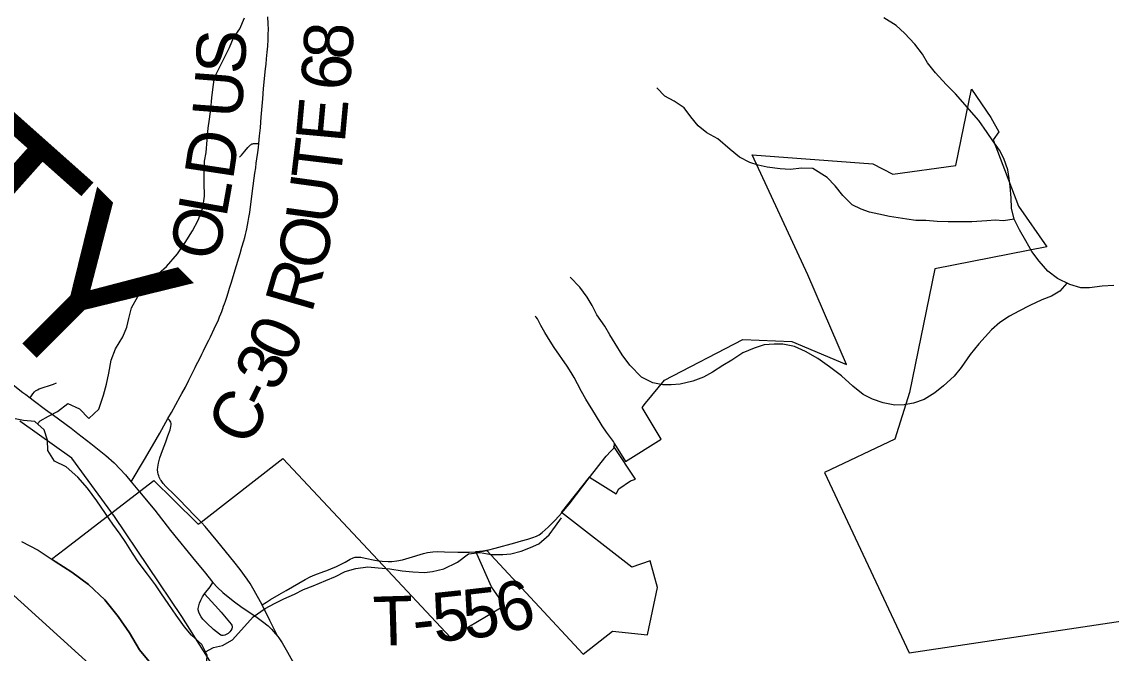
# Model space of a CAD drawing. Extents: x 0 to 34, y 0 to 22.
# Drawn here: x 4.632 to 5.89, y 17.888 to 18.618 of the extents above; entities that cross this region are included whole.
import ezdxf

# ---------------------------------------------------------------- set-up
doc = ezdxf.new("R2010")
doc.units = 0
for name, color, linetype in [('Default', 7, 'Continuous'), ('GM_X_City_Street', 7, 'Continuous'), ('GM_X_Corporation', 7, 'Continuous'), ('GM_X_County_Road', 7, 'Continuous'), ('GM_X_County_Road_Text', 7, 'Continuous'), ('GM_X_County_Text', 7, 'Continuous'), ('GM_X_Major_River', 7, 'Continuous'), ('GM_X_Minor_River', 7, 'Continuous'), ('GM_X_Rail_Line', 7, 'Continuous'), ('GM_X_Township_Road', 7, 'Continuous'), ('GM_X_Township_Road_Text', 7, 'Continuous'), ('GM_X_US_Route', 7, 'Continuous'), ('SH_Cut_Line', 7, 'Continuous'), ('SH_Text', 7, 'Continuous')]:
    doc.layers.add(name, color=color, linetype=linetype)

msp = doc.modelspace()

# ---------------------------------------------------------------- linework, layer by layer
at = {"layer": 'Default'}
msp.add_lwpolyline([(4.6315, 18.0174), (4.6508, 18.0075), (4.6705, 17.9942), (4.6895, 17.9821), (4.7088, 17.9676), (4.7278, 17.9502), (4.7433, 17.9308), (4.7562, 17.9118), (4.7676, 17.8924), (4.7846, 17.8719)], dxfattribs=at)
at = {"layer": 'GM_X_City_Street'}
msp.add_lwpolyline([(4.8429, 17.9568), (4.8588, 17.9394), (4.8621, 17.9356), (4.8736, 17.9218), (4.8742, 17.9208), (4.8746, 17.919), (4.8747, 17.9177), (4.8743, 17.9166), (4.8731, 17.9144), (4.872, 17.9129), (4.8701, 17.9113), (4.868, 17.9099), (4.8663, 17.9092), (4.8645, 17.9088), (4.8627, 17.9089), (4.8615, 17.9093), (4.86, 17.9103), (4.8531, 17.9157), (4.8455, 17.9229), (4.8408, 17.9278), (4.8389, 17.9303), (4.8374, 17.933), (4.8362, 17.9359), (4.8356, 17.9383), (4.8356, 17.9402), (4.8361, 17.9432), (4.837, 17.9462), (4.8385, 17.9496), (4.8406, 17.9534), (4.8429, 17.9568), (4.8495, 17.965), (4.8525, 17.9701)], dxfattribs=at)
at = {"layer": 'GM_X_Corporation'}
msp.add_lwpolyline([(4.7846, 17.8719), (4.7676, 17.8924), (4.7562, 17.9118), (4.7433, 17.9308), (4.7278, 17.9502), (4.7088, 17.9676), (4.6895, 17.9821), (4.6663, 17.9971), (4.6822, 18.0093), (4.7676, 18.0753), (4.7844, 18.0881), (4.8072, 18.0655), (4.8356, 18.0375), (4.8391, 18.0399), (4.8408, 18.0412), (4.9332, 18.1133), (5.0434, 17.9957), (5.1269, 17.9065), (5.1893, 17.9436), (5.1743, 17.9652), (5.156, 18.0059), (5.1642, 18.0067), (5.1685, 18.0075), (5.2802, 17.8874), (5.3138, 17.9139), (5.3542, 17.9096), (5.3658, 17.9643), (5.3573, 17.995), (5.3363, 17.9878), (5.2549, 18.0509), (5.2872, 18.0918), (5.3182, 18.0725), (5.3211, 18.0782), (5.3347, 18.0874), (5.3403, 18.0894), (5.3156, 18.1272), (5.3161, 18.1289), (5.3161, 18.1302), (5.3291, 18.11), (5.37, 18.1357), (5.348, 18.1723), (5.3521, 18.1772), (5.3739, 18.2038), (5.4644, 18.2508), (5.5208, 18.2485), (5.584, 18.2221), (5.5394, 18.3257), (5.4753, 18.4644), (5.6144, 18.4541), (5.6375, 18.4422), (5.7102, 18.452), (5.7284, 18.5403), (5.7506, 18.5077), (5.7599, 18.4908), (5.7535, 18.4818), (5.7825, 18.4049), (5.8153, 18.3581), (5.6861, 18.3327), (5.657, 18.1896), (5.6398, 18.1359), (5.5587, 18.0971), (5.6566, 17.8886), (5.9367, 17.9306)], dxfattribs=at)
at = {"layer": 'GM_X_County_Road'}
for points in [[(4.9056, 18.4775), (4.9065, 18.4865), (4.9074, 18.4954), (4.9079, 18.5023), (4.9084, 18.5078), (4.9102, 18.529), (4.9111, 18.5409), (4.9133, 18.5636), (4.9139, 18.5693), (4.9145, 18.5752), (4.9152, 18.5829), (4.9158, 18.5901), (4.9162, 18.5977), (4.9165, 18.6034), (4.9166, 18.6095), (4.9164, 18.6156), (4.9158, 18.6237)], [(4.8006, 18.1596), (4.8046, 18.1665), (4.8148, 18.1849), (4.8168, 18.1887), (4.8207, 18.1958), (4.8249, 18.2041), (4.8299, 18.214), (4.8321, 18.2185), (4.8337, 18.2219), (4.8365, 18.2274), (4.8397, 18.2341), (4.8416, 18.238), (4.8446, 18.2442), (4.8477, 18.2503), (4.8496, 18.2542), (4.8539, 18.2631), (4.8588, 18.2738), (4.8603, 18.2771), (4.8617, 18.2806), (4.8628, 18.2834), (4.8639, 18.2866), (4.8649, 18.2896), (4.8658, 18.292), (4.8669, 18.2953), (4.8684, 18.2997), (4.8701, 18.3048), (4.8718, 18.3101), (4.8739, 18.3172), (4.8781, 18.3316), (4.8838, 18.3503), (4.886, 18.3575), (4.8883, 18.365), (4.8893, 18.3688), (4.8902, 18.3721), (4.8909, 18.3752), (4.8917, 18.3789), (4.8926, 18.383), (4.8934, 18.3873), (4.8941, 18.3919), (4.895, 18.3978), (4.8959, 18.4041), (4.8972, 18.4131), (4.8984, 18.4228), (4.9011, 18.4433), (4.9019, 18.4495), (4.9026, 18.4546), (4.9033, 18.4597), (4.9043, 18.4671), (4.9051, 18.473), (4.9056, 18.4775)], [(4.7583, 18.0865), (4.7737, 18.1122), (4.7828, 18.1281), (4.7911, 18.1428), (4.8006, 18.1596)]]:
    msp.add_lwpolyline(points, dxfattribs=at)
at = {"layer": 'GM_X_Major_River'}
for points in [[(4.7663, 17.994), (4.7596, 18.0039), (4.7518, 18.0162), (4.7455, 18.0258), (4.737, 18.0373), (4.7284, 18.0499), (4.7184, 18.0644), (4.7079, 18.079), (4.6964, 18.0917), (4.6829, 18.1036), (4.6697, 18.1102), (4.6619, 18.1225), (4.6617, 18.1346), (4.6577, 18.1465), (4.6468, 18.1561), (4.6339, 18.1574), (4.6241, 18.1594)], [(4.8727, 17.8128), (4.8582, 17.8361), (4.8535, 17.8479), (4.8502, 17.8605), (4.8451, 17.8723), (4.846, 17.8859), (4.8397, 17.8985), (4.8277, 17.9093), (4.8199, 17.9189), (4.8102, 17.9323), (4.8017, 17.9446), (4.7924, 17.958), (4.7864, 17.9675), (4.7771, 17.9798), (4.7663, 17.994)]]:
    msp.add_lwpolyline(points, dxfattribs=at)
at = {"layer": 'GM_X_Minor_River'}
for points in [[(4.6499, 18.1533), (4.653, 18.1568), (4.6626, 18.1624), (4.6729, 18.1679), (4.6851, 18.1769), (4.6983, 18.1706), (4.7092, 18.1595), (4.7207, 18.1703), (4.7262, 18.1866), (4.7297, 18.1994), (4.7322, 18.2119), (4.735, 18.227), (4.7401, 18.2402), (4.7486, 18.2542), (4.7533, 18.2651), (4.7553, 18.2753), (4.7585, 18.2874), (4.7659, 18.3006), (4.7767, 18.3141), (4.7863, 18.3242), (4.7989, 18.3354), (4.8116, 18.35), (4.8205, 18.3632), (4.829, 18.3767), (4.8356, 18.3888), (4.8407, 18.4031), (4.8428, 18.4164), (4.8426, 18.4323), (4.8424, 18.4448), (4.8429, 18.457), (4.8446, 18.4672), (4.8459, 18.4816), (4.8472, 18.4952), (4.8485, 18.5054), (4.8501, 18.5172), (4.8514, 18.5304), (4.8527, 18.5429), (4.8544, 18.5539), (4.8614, 18.5678), (4.8664, 18.5776), (4.8715, 18.5886), (4.8762, 18.5995), (4.8835, 18.61), (4.889, 18.6228)], [(5.8928, 18.3133), (5.8792, 18.3124), (5.8647, 18.3107), (5.8545, 18.3108), (5.842, 18.3144), (5.8277, 18.3214), (5.8165, 18.3299), (5.8064, 18.3414), (5.7982, 18.3525), (5.7911, 18.3651), (5.7837, 18.3777), (5.7778, 18.39), (5.7745, 18.4029), (5.7743, 18.4147), (5.7729, 18.4276), (5.7719, 18.4371), (5.7702, 18.4469), (5.7658, 18.4603), (5.7606, 18.4698), (5.7531, 18.4805), (5.7464, 18.4901), (5.7368, 18.5039), (5.7285, 18.5135), (5.7184, 18.5254), (5.7098, 18.535), (5.699, 18.5457), (5.687, 18.5592), (5.6777, 18.5707), (5.6718, 18.5806), (5.6628, 18.5921), (5.6512, 18.6048), (5.6415, 18.614), (5.6272, 18.6229)], [(5.7777, 18.3902), (5.7652, 18.3882), (5.7558, 18.3887), (5.7463, 18.3881), (5.7288, 18.3868), (5.711, 18.387), (5.7015, 18.3868), (5.6887, 18.3873), (5.6758, 18.3883), (5.664, 18.3884), (5.6538, 18.3901), (5.6436, 18.3914), (5.6338, 18.393), (5.6213, 18.3958), (5.6107, 18.3982), (5.6009, 18.4014), (5.5907, 18.4065), (5.5798, 18.4172), (5.5709, 18.4287), (5.5619, 18.4383), (5.5454, 18.4484), (5.5325, 18.449), (5.5192, 18.4476), (5.5074, 18.4482), (5.4923, 18.4503), (5.4821, 18.4523), (5.4723, 18.4555), (5.4606, 18.4617), (5.4497, 18.4705), (5.4355, 18.4829), (5.4227, 18.4899), (5.4129, 18.498), (5.4043, 18.5083), (5.3965, 18.5187), (5.3852, 18.5264), (5.3743, 18.5322), (5.3649, 18.5418)], [(5.8384, 18.3162), (5.8306, 18.3066), (5.8206, 18.301), (5.8096, 18.2966), (5.7959, 18.2903), (5.7829, 18.2837), (5.7722, 18.2778), (5.7611, 18.2707), (5.7515, 18.2621), (5.7369, 18.246), (5.7269, 18.2336), (5.7165, 18.2186), (5.7084, 18.2085), (5.6961, 18.1972), (5.6862, 18.1894), (5.6736, 18.1816), (5.6614, 18.1772), (5.6507, 18.1755), (5.6397, 18.1752), (5.6265, 18.1777), (5.614, 18.182), (5.6035, 18.1875), (5.5915, 18.1971), (5.5784, 18.209), (5.5645, 18.2195), (5.5509, 18.2291), (5.5366, 18.2369), (5.5242, 18.2428), (5.5106, 18.2456), (5.5007, 18.2457), (5.489, 18.2447), (5.4775, 18.2411), (5.4642, 18.2356), (5.4516, 18.227), (5.4413, 18.2207), (5.4294, 18.2133), (5.4191, 18.2074), (5.4065, 18.2026), (5.3921, 18.1994), (5.3815, 18.1984), (5.372, 18.1985), (5.3603, 18.2009), (5.3474, 18.2072), (5.334, 18.2214), (5.325, 18.2333), (5.3169, 18.2463), (5.3109, 18.2562), (5.305, 18.2665), (5.296, 18.2795), (5.2905, 18.2902), (5.2845, 18.2998), (5.2763, 18.3113), (5.2651, 18.3228)], [(4.8439, 17.8901), (4.8533, 17.8948), (4.8636, 17.8973), (4.875, 17.9039), (4.8989, 17.9302), (4.913, 17.9399), (4.9237, 17.9458), (4.9344, 17.951), (4.9466, 17.9565), (4.9573, 17.962), (4.9683, 17.9664), (4.9828, 17.9723), (4.9942, 17.9771), (5.0053, 17.9826), (5.0175, 17.9863), (5.0315, 17.988), (5.0433, 17.9871), (5.0569, 17.9857), (5.0709, 17.9837), (5.0834, 17.9824), (5.0967, 17.9818), (5.1062, 17.9828), (5.1191, 17.9857), (5.1351, 17.9934), (5.1477, 18.0031), (5.161, 18.0048), (5.1739, 18.0024), (5.1872, 18.0026), (5.1966, 18.0032), (5.2084, 18.0061), (5.2191, 18.0105), (5.229, 18.0146), (5.2409, 18.025), (5.2482, 18.0352), (5.2552, 18.0449)]]:
    msp.add_lwpolyline(points, dxfattribs=at)
at = {"layer": 'GM_X_Rail_Line'}
msp.add_lwpolyline([(5.3956, 16.5475), (5.3342, 16.7534), (5.2911, 16.8846), (5.2194, 17.0664), (5.139, 17.2492), (5.1192, 17.3014), (5.1029, 17.346), (5.0833, 17.3922), (5.0098, 17.5633), (4.954, 17.6832), (4.8916, 17.8118), (4.8168, 17.9308), (4.739, 18.0464), (4.6895, 18.1137), (4.6296, 18.1567)], dxfattribs=at)
at = {"layer": 'GM_X_Township_Road'}
msp.add_line((5.3158, 18.1266), (5.3163, 18.1284), dxfattribs=at)
for points in [[(4.8832, 18.4615), (4.8855, 18.4641), (4.8893, 18.4687), (4.8928, 18.4729), (4.894, 18.4741), (4.8954, 18.4755), (4.8961, 18.476), (4.8968, 18.4765), (4.8976, 18.4769), (4.8985, 18.4772), (4.8994, 18.4774), (4.9003, 18.4775), (4.902, 18.4775), (4.9056, 18.4775)], [(5.3163, 18.1284), (5.3164, 18.1297), (5.316, 18.1314), (5.3152, 18.1331), (5.3069, 18.144), (5.3021, 18.1512), (5.2944, 18.1639), (5.2832, 18.1818), (5.278, 18.191), (5.2733, 18.1997), (5.2696, 18.2069), (5.2662, 18.2128), (5.2615, 18.2201), (5.2467, 18.2416), (5.2419, 18.2489), (5.2357, 18.2589), (5.2311, 18.267), (5.2272, 18.2747), (5.2258, 18.2768), (5.2245, 18.278)], [(4.6415, 18.1836), (4.6446, 18.188), (4.6464, 18.1904), (4.6477, 18.1916), (4.6498, 18.1929), (4.652, 18.194), (4.6567, 18.1955), (4.6639, 18.1977), (4.6686, 18.1994), (4.6719, 18.201)], [(4.7904, 18.0919), (4.7899, 18.0934), (4.7894, 18.0952), (4.7889, 18.0976), (4.7887, 18.1001), (4.7888, 18.1032), (4.7897, 18.108), (4.7913, 18.1141), (4.7943, 18.1228), (4.7981, 18.1327), (4.8006, 18.1397), (4.8031, 18.1467), (4.8041, 18.1502), (4.8043, 18.1525), (4.8043, 18.1539), (4.804, 18.1554), (4.8033, 18.1565), (4.8024, 18.1576), (4.8006, 18.1596)], [(5.2871, 18.091), (5.2927, 18.0982), (5.3009, 18.1089), (5.3067, 18.1159), (5.312, 18.1218), (5.3149, 18.125), (5.3158, 18.1266)], [(4.8393, 18.0394), (4.8315, 18.0473), (4.8136, 18.0661), (4.8079, 18.0718), (4.798, 18.0811), (4.7951, 18.0843), (4.7926, 18.0878), (4.792, 18.0887), (4.7915, 18.0896), (4.7904, 18.0919)], [(5.2553, 18.0506), (5.2574, 18.053), (5.2638, 18.0605), (5.2724, 18.0717), (5.2859, 18.0894), (5.2871, 18.091)], [(4.9093, 17.9441), (4.9003, 17.961), (4.8956, 17.969), (4.892, 17.9741), (4.884, 17.9851), (4.8767, 17.9944), (4.8583, 18.017), (4.8436, 18.0347), (4.8393, 18.0394)], [(5.1697, 18.0073), (5.1786, 18.0098), (5.2013, 18.016), (5.209, 18.0183), (5.2161, 18.0203), (5.222, 18.0222), (5.226, 18.0235), (5.2293, 18.0251), (5.2325, 18.0278), (5.2396, 18.0341), (5.2477, 18.042), (5.2553, 18.0506)], [(5.0447, 17.9951), (5.0478, 17.9948), (5.0547, 17.9944), (5.059, 17.9945), (5.065, 17.9952), (5.0715, 17.9964), (5.0792, 17.9984), (5.0955, 18.0036), (5.1003, 18.0047), (5.1065, 18.0055), (5.112, 18.0058), (5.1201, 18.0057), (5.1355, 18.0051), (5.1484, 18.0053)], [(5.1484, 18.0053), (5.1563, 18.0054), (5.1573, 18.0055)], [(5.1573, 18.0055), (5.1644, 18.0062), (5.1687, 18.007), (5.1697, 18.0073)], [(4.9093, 17.9441), (4.9143, 17.9473), (4.9191, 17.9503), (4.9292, 17.9563), (4.9372, 17.961), (4.959, 17.9736), (4.965, 17.9767), (4.9701, 17.979), (4.9805, 17.9828), (4.984, 17.9841), (4.9885, 17.986), (4.9954, 17.9887), (4.9992, 17.9906), (5.0051, 17.9937), (5.011, 17.997), (5.0144, 17.9985), (5.0167, 17.9992), (5.0197, 17.9995), (5.0233, 17.9992), (5.0284, 17.9982), (5.0393, 17.9959), (5.0436, 17.9952), (5.0447, 17.9951)], [(4.9274, 17.9077), (4.9182, 17.9262), (4.9093, 17.9441)]]:
    msp.add_lwpolyline(points, dxfattribs=at)
at = {"layer": 'GM_X_US_Route'}
msp.add_line((4.7583, 18.0865), (4.7678, 18.0748), dxfattribs=at)
for points in [[(4.6027, 18.2134), (4.633, 18.1898), (4.6365, 18.1873), (4.6415, 18.1836), (4.645, 18.181), (4.6594, 18.1702), (4.6683, 18.1634), (4.6889, 18.1484), (4.6967, 18.1423), (4.7115, 18.1309), (4.7288, 18.1169), (4.7385, 18.1083), (4.7454, 18.1012), (4.7516, 18.0944), (4.7583, 18.0865)], [(4.7678, 18.0748), (4.7853, 18.0536), (4.8037, 18.0303), (4.8325, 17.9947), (4.8423, 17.9827), (4.8525, 17.9701), (4.8579, 17.9643), (4.864, 17.9587), (4.87, 17.9535), (4.8773, 17.9478), (4.8864, 17.9413), (4.9019, 17.9309), (4.9099, 17.925), (4.9162, 17.9199), (4.9203, 17.916), (4.9249, 17.9109), (4.9274, 17.9077), (4.9288, 17.906), (4.9325, 17.9003), (4.9341, 17.8976)], [(4.9341, 17.8976), (4.9388, 17.8896), (4.9478, 17.8731), (4.9638, 17.8437), (4.9719, 17.8286), (4.9785, 17.816), (4.9949, 17.7837), (4.9972, 17.7796), (5.0109, 17.7548), (5.0234, 17.7307), (5.0349, 17.7066), (5.044, 17.6874), (5.0525, 17.6693), (5.0594, 17.6541), (5.0662, 17.6395), (5.0858, 17.5952), (5.0871, 17.5923), (5.0934, 17.5789), (5.099, 17.5667), (5.1018, 17.5606), (5.1147, 17.5324), (5.1201, 17.5189), (5.1284, 17.4994)]]:
    msp.add_lwpolyline(points, dxfattribs=at)
at = {"layer": 'SH_Cut_Line'}
msp.add_lwpolyline([(4.6315, 18.0174), (4.6508, 18.0075), (4.6705, 17.9942), (4.6895, 17.9821), (4.7088, 17.9676), (4.7278, 17.9502), (4.7433, 17.9308), (4.7562, 17.9118), (4.7676, 17.8924), (4.7846, 17.8719)], dxfattribs=at)
at = {"layer": 'SH_Text'}
msp.add_lwpolyline([(4.4348, 17.7221), (4.9594, 17.6492), (4.4349, 18.1254)], close=True, dxfattribs=at)

# ---------------------------------------------------------------- texts
at = {"layer": 'GM_X_County_Road_Text'}
for s, rotation, p in [('S', 86.9949, (4.8891, 18.5569)), ('8', 86.5253, (5.0131, 18.5736)), ('6', 85.1848, (5.01, 18.5373)), ('U', 85.6168, (4.8852, 18.5056)), ('E', 84.7583, (5.0046, 18.4771)), ('D', 81.3925, (4.8756, 18.4342)), ('T', 83.1148, (4.9993, 18.4331)), ('L', 79.9091, (4.8679, 18.3907)), ('U', 82.153, (4.9924, 18.3825)), ('O', 77.9931, (4.8571, 18.3398)), ('O', 77.288, (4.9804, 18.3286)), ('R', 73.8573, (4.9665, 18.2802)), ('0', 65.974, (4.9421, 18.2219)), ('3', 64.1969, (4.9261, 18.1886)), ('C', 63.4424, (4.8945, 18.1252)), ('-', 63.6066, (4.9154, 18.1671))]:
    msp.add_text(s, height=0.0568, rotation=rotation, dxfattribs=at).set_placement(p)
at = {"layer": 'GM_X_County_Text'}
for s, rotation, p in [('T', 318.3233, (4.4774, 18.3898)), ('Y', 315.0269, (4.5811, 18.2976))]:
    msp.add_text(s, height=0.1894, rotation=rotation, dxfattribs=at).set_placement(p)
at = {"layer": 'GM_X_Township_Road_Text'}
for s, rotation, p in [('5', 6.4271, (5.1439, 17.9046)), ('6', 14.8654, (5.1876, 17.9102)), ('T', 1.677, (5.0382, 17.8968)), ('5', 6.1028, (5.1088, 17.9009)), ('-', 6.1978, (5.0856, 17.8984))]:
    msp.add_text(s, height=0.0568, rotation=rotation, dxfattribs=at).set_placement(p)

doc.saveas('drawing.dxf')
